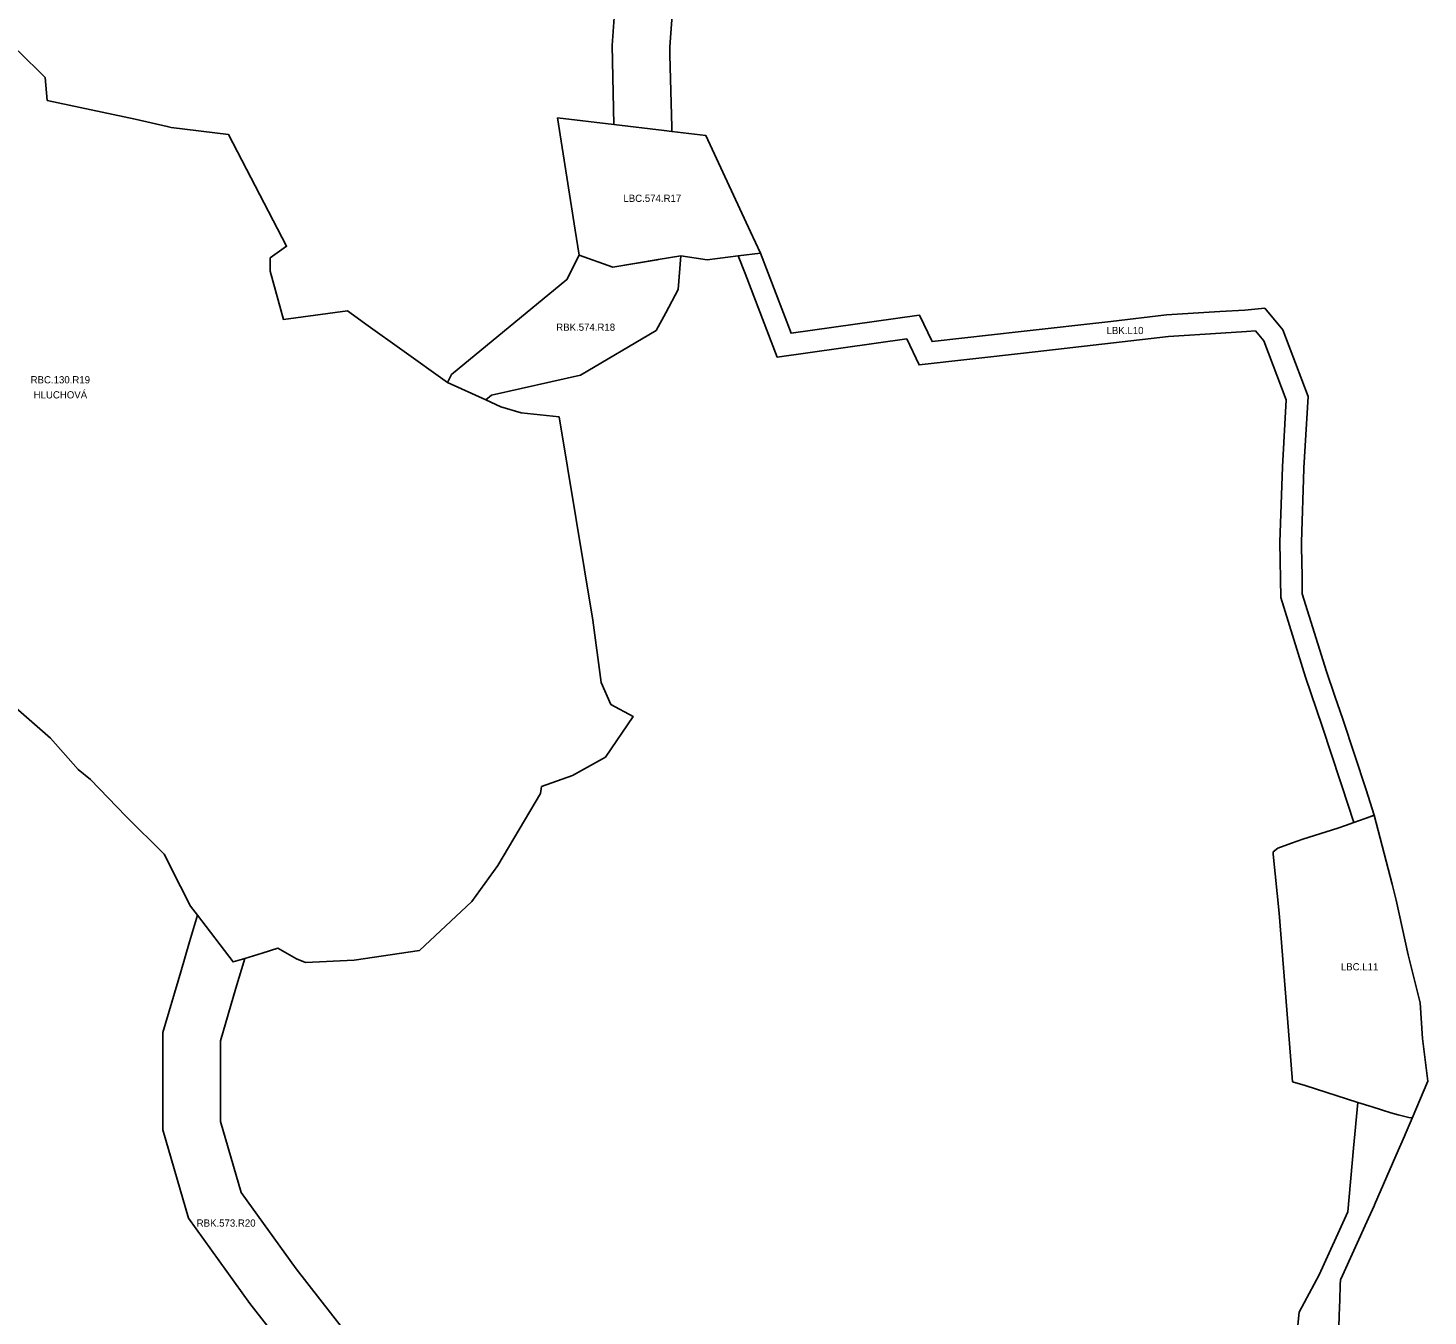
# Model space of a CAD drawing. Extents: x -450188 to -432919, y -1130252 to -1121189.
# Drawn here: x -435829 to -433885, y -1128604 to -1126816 of the extents above; entities that cross this region are included whole.
import ezdxf

# ---------------------------------------------------------------- set-up
doc = ezdxf.new("R2010")
doc.units = 0
for name, color, linetype in [('Vrstva 30', 7, 'Continuous'), ('Vrstva 31', 7, 'Continuous'), ('Vrstva 32', 7, 'Continuous'), ('Vrstva 33', 7, 'Continuous'), ('Vrstva 36', 7, 'Continuous')]:
    doc.layers.add(name, color=color, linetype=linetype)

msp = doc.modelspace()

# ---------------------------------------------------------------- linework, layer by layer
at = {"layer": 'Vrstva 30'}
for p, q in [((-435309.8, -1127262.9), (-435246.4, -1127308)), ((-435246.4, -1127308), (-435193.2, -1127332.3))]:
    msp.add_line(p, q, dxfattribs=at)
for points in [[(-435842.2, -1126847.6), (-435804.8, -1126885), (-435802, -1126916.7), (-435680, -1126942.8), (-435635.5, -1126952.8), (-435629.9, -1126954.1), (-435550.3, -1126964), (-435469.8, -1127119.1), (-435492.4, -1127135.3), (-435492.4, -1127153.6), (-435474.1, -1127220.6), (-435385.3, -1127208.6), (-435356.4, -1127229.4), (-435309.8, -1127262.9)], [(-435193.2, -1127332.3), (-435193.2, -1127332.3), (-435172.3, -1127341.9), (-435144.1, -1127350.3), (-435091.3, -1127356), (-435044.7, -1127638), (-435032.7, -1127724.7), (-435019.3, -1127755.1), (-434988.3, -1127772), (-435027.1, -1127828.4), (-435072.9, -1127853.8), (-435115.6, -1127869.2), (-435117.3, -1127878.9), (-435176.3, -1127978.7), (-435212.6, -1128028.6), (-435285.1, -1128096.6), (-435375.9, -1128110.2), (-435443.3, -1128113.4), (-435456, -1128108.2), (-435481.7, -1128093.4), (-435503.6, -1128100.1), (-435527.7, -1128107.5), (-435543.9, -1128112.5), (-435593.4, -1128047.7), (-435603.1, -1128035), (-435617.1, -1128007.6), (-435639.8, -1127963.1), (-435692.7, -1127910.2), (-435742, -1127859.4), (-435759.2, -1127845.4), (-435797.7, -1127801.8), (-436047.1, -1127584.1)]]:
    msp.add_lwpolyline(points, dxfattribs=at)
at = {"layer": 'Vrstva 31'}
for p, q in [((-435063.4, -1127131.5), (-435016.9, -1127148)), ((-435246.4, -1127308), (-435240.7, -1127297))]:
    msp.add_line(p, q, dxfattribs=at)
for points in [[(-435015.1, -1126950.3), (-435017.7, -1126840.5), (-435011, -1126749.5), (-435003.8, -1126712.6), (-435001.1, -1126698.6), (-434996.5, -1126674.9), (-434984.3, -1126612.1), (-435002.3, -1126605.2), (-435058, -1126609.8)], [(-434920.2, -1126701.9), (-434920.7, -1126704), (-434920.7, -1126704.1), (-434931.6, -1126760.1), (-434937.7, -1126842.4), (-434937.4, -1126853.5), (-434935, -1126953.6), (-434934.8, -1126959.8)], [(-434934.8, -1126959.8), (-434945.3, -1126958.6), (-435015.1, -1126950.3)], [(-435016.9, -1127148), (-434953.8, -1127137.6), (-434922.1, -1127132.4), (-434925.8, -1127179.2), (-434943.3, -1127211.6), (-434956.4, -1127235.9), (-435061.6, -1127298.2), (-435185.2, -1127326), (-435193.2, -1127332.3), (-435246.4, -1127308)], [(-435240.7, -1127297), (-435080.5, -1127165.4), (-435063.4, -1127131.5)], [(-435357.8, -1128794.5), (-435405.9, -1128733.1), (-435520.6, -1128586.6), (-435605.8, -1128468.3), (-435641.6, -1128345.5), (-435641.6, -1128210.4), (-435616.7, -1128126.2), (-435604.4, -1128084.8), (-435593.4, -1128047.7), (-435543.9, -1128112.5), (-435527.7, -1128107.5), (-435540, -1128149), (-435561.6, -1128222.1), (-435561.6, -1128334), (-435532.8, -1128432.7), (-435456.6, -1128538.6), (-435342.9, -1128683.8), (-435324.9, -1128706.8)]]:
    msp.add_lwpolyline(points, dxfattribs=at)
at = {"layer": 'Vrstva 32'}
for p, q in [((-435015.1, -1126950.3), (-434945.3, -1126958.6)), ((-434945.3, -1126958.6), (-434934.8, -1126959.8)), ((-434811.7, -1127128.8), (-434842.7, -1127132.6)), ((-435016.9, -1127148), (-435063.4, -1127131.5)), ((-433959.4, -1127908.9), (-433934.7, -1128004.5))]:
    msp.add_line(p, q, dxfattribs=at)
for points in [[(-435063.4, -1127131.5), (-435068.9, -1127096.9), (-435093.5, -1126940.9), (-435015.1, -1126950.3)], [(-434934.8, -1126959.8), (-434887.4, -1126965.5), (-434825.5, -1127099.1), (-434811.7, -1127128.8)], [(-434842.7, -1127132.6), (-434885.6, -1127137.9), (-434922.1, -1127132.4), (-434953.8, -1127137.6), (-434955.2, -1127137.9), (-435016.9, -1127148)], [(-433926.3, -1128324.6), (-433936.5, -1128322.1), (-433962.5, -1128313.8), (-433982.2, -1128307.6), (-434055.5, -1128284.2), (-434073, -1128278.7), (-434077.2, -1128225.8), (-434091.7, -1128044.9), (-434099.7, -1127963), (-434100, -1127959.7), (-434093.6, -1127954.4), (-434074.4, -1127947.4), (-434058.6, -1127942.2), (-434010.2, -1127926.8), (-433999.4, -1127923), (-433987.8, -1127918.9)], [(-433987.8, -1127918.9), (-433972.2, -1127913.4), (-433959.4, -1127908.9)], [(-433934.7, -1128004.5), (-433928.9, -1128026.9), (-433912.3, -1128102.5), (-433895.6, -1128169.1), (-433892.4, -1128218.8), (-433884.9, -1128278), (-433907, -1128329.4)], [(-433907, -1128329.4), (-433908.1, -1128329.1), (-433911.5, -1128328.2), (-433926.3, -1128324.6)]]:
    msp.add_lwpolyline(points, dxfattribs=at)
at = {"layer": 'Vrstva 33'}
for p, q in [((-434842.7, -1127132.6), (-434811.7, -1127128.8)), ((-433982.2, -1128307.6), (-433962.5, -1128313.8)), ((-433962.5, -1128313.8), (-433936.5, -1128322.1)), ((-433908.1, -1128329.1), (-433907, -1128329.4))]:
    msp.add_line(p, q, dxfattribs=at)
for points in [[(-434811.7, -1127128.8), (-434769.2, -1127239.9), (-434594.8, -1127215.3), (-434590.9, -1127214.8), (-434573.5, -1127251.5), (-434449.9, -1127237.5), (-434325.1, -1127223.4), (-434247.8, -1127214.4), (-434174.1, -1127209.5), (-434139.1, -1127207.7), (-434111.6, -1127205.2), (-434086.4, -1127234.9), (-434051.3, -1127327.5), (-434055.4, -1127396.2), (-434057.2, -1127426.8), (-434057.2, -1127428), (-434060.6, -1127529.9), (-434060.5, -1127536.1), (-434059.8, -1127577.4), (-434059.4, -1127601.7), (-434028.1, -1127702.1), (-434026.3, -1127707.8), (-434014, -1127743.8), (-434003.1, -1127775.5), (-433970.9, -1127873.8), (-433959.4, -1127908.9), (-433961.4, -1127909.6)], [(-433961.4, -1127909.6), (-433972.2, -1127913.4), (-433987.8, -1127918.9), (-433988.2, -1127917.4), (-433989.5, -1127913.4), (-433994.2, -1127899.2), (-434006.2, -1127862.5), (-434031.6, -1127785), (-434054.8, -1127717.1), (-434089.3, -1127606.6), (-434090.7, -1127529.7), (-434087.1, -1127425.4), (-434081.6, -1127332.1), (-434112.6, -1127250.3), (-434124.4, -1127236.5), (-434137, -1127237.6), (-434172.3, -1127239.5), (-434245.1, -1127244.3), (-434321.7, -1127253.2), (-434446.6, -1127267.3), (-434591.4, -1127283.7), (-434608.5, -1127247.6), (-434788.7, -1127272.9), (-434833.1, -1127156.7), (-434842.7, -1127132.6)], [(-434063.9, -1128598.6), (-434036.2, -1128546.8), (-433996.4, -1128459.3), (-433988.2, -1128371.2), (-433982.2, -1128307.6)], [(-433907, -1128329.4), (-433909.8, -1128336), (-433916.6, -1128351.8), (-433917.7, -1128354.2), (-433929.6, -1128381.8), (-433959, -1128449.7), (-433959.3, -1128450.3), (-433967.5, -1128468.3), (-434006.1, -1128553), (-434006.5, -1128553.8), (-434006.7, -1128560.7), (-434007.4, -1128582), (-434007.8, -1128591.9), (-434008.2, -1128603.5), (-434009.2, -1128634.4)], [(-433936.5, -1128322.1), (-433926.3, -1128324.6), (-433911.5, -1128328.2), (-433908.1, -1128329.1)], [(-434073.1, -1128689.1), (-434063.9, -1128598.6)]]:
    msp.add_lwpolyline(points, dxfattribs=at)

# ---------------------------------------------------------------- texts
at = {"layer": 'Vrstva 36'}
for s, p in [('LBC.574.R17', (-435002, -1127057.5)), ('RBK.574.R18', (-435095.3, -1127236.4)), ('LBK.L10', (-434331.2, -1127241)), ('RBC.130.R19', (-435825.1, -1127309.4)), ('HLUCHOVÁ', (-435820.9, -1127330.3)), ('LBC.L11', (-434005.9, -1128124.2)), ('RBK.573.R20', (-435594.5, -1128479.9))]:
    msp.add_text(s, height=10, dxfattribs=at).set_placement(p)

doc.saveas('drawing.dxf')
